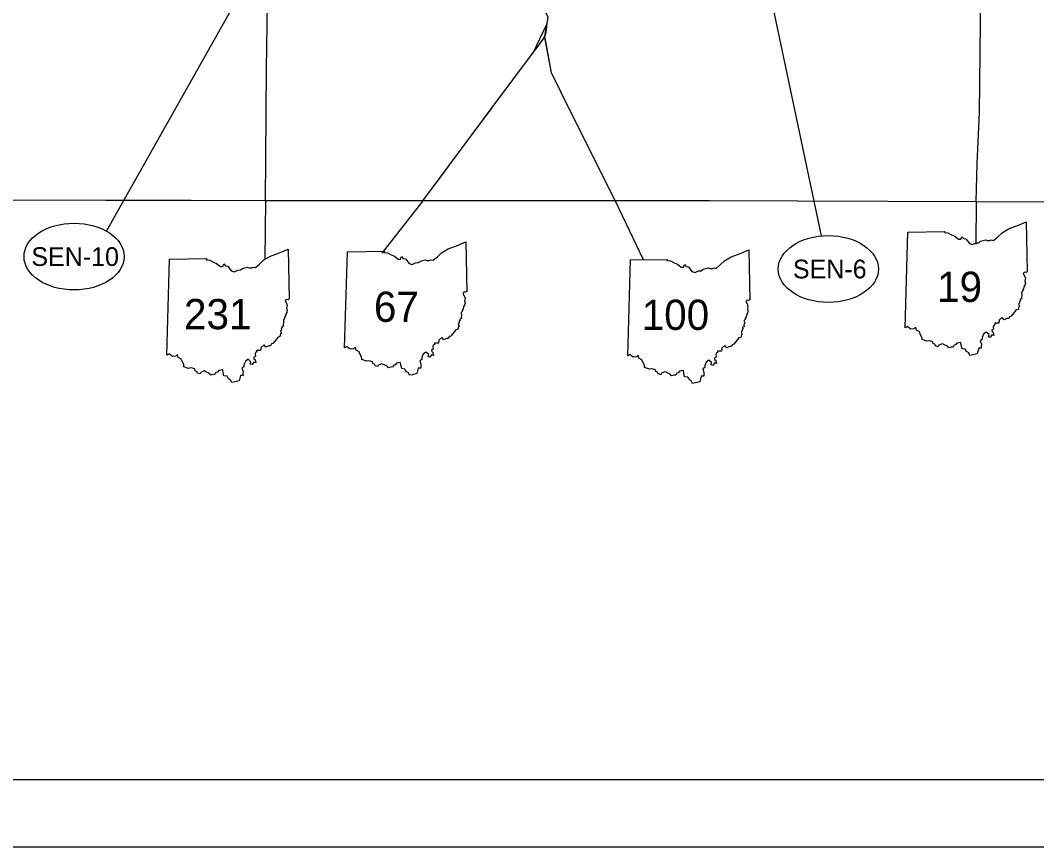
# Model space of a CAD drawing. Extents: x 0 to 882, y 0 to 440.
# Drawn here: x 275.2 to 427.4, y 0 to 123.7 of the extents above; entities that cross this region are included whole.
import ezdxf

# ---------------------------------------------------------------- set-up
doc = ezdxf.new("R2010")
doc.units = 0
for name, color, linetype in [('GM_X_County', 7, 'Continuous'), ('GM_X_State_Route', 7, 'Continuous'), ('PV_P_Text', 7, 'Continuous'), ('RD_P_Fence', 7, 'Continuous'), ('SH_Border', 7, 'Continuous'), ('SH_Cut_Line', 7, 'Continuous'), ('SH_Data', 7, 'Continuous')]:
    doc.layers.add(name, color=color, linetype=linetype)

msp = doc.modelspace()

# ---------------------------------------------------------------- linework, layer by layer
at = {"layer": 'GM_X_County'}
msp.add_lwpolyline([(431.55, 96.47), (418.34, 96.52), (405.13, 96.59), (391.64, 96.65), (391.54, 96.65), (378.39, 96.68), (378.35, 96.67), (364.27, 96.7), (351.77, 96.69), (343.39, 96.66), (338.49, 96.67), (335.48, 96.66), (317.08, 96.69), (311.95, 96.7), (300.8, 96.71), (298.62, 96.72), (288.73, 96.73), (288.04, 96.73), (272.14, 96.76)], dxfattribs=at)
at = {"layer": 'GM_X_State_Route'}
for p, q in [((311.95, 96.7), (311.86, 87.89)), ((335.48, 96.66), (329.38, 88.85)), ((364.27, 96.7), (368.48, 87.89)), ((418.34, 96.52), (418.3, 90.19))]:
    msp.add_line(p, q, dxfattribs=at)
for points in [[(312.11, 116.42), (312.31, 129.67), (312.36, 136.32), (312.5, 150.5), (312.51, 150.79), (312.57, 153.89), (312.59, 154.82), (312.59, 155.09), (312.23, 156.32)], [(418.34, 96.52), (418.48, 102.28), (418.83, 109.89), (418.99, 123.29), (418.97, 125.8), (418.52, 128.47), (418.31, 129.89), (417.67, 133.85), (417.69, 134.46), (417.82, 135.31), (418.05, 136.45), (418.22, 137.09), (418.36, 137.45), (418.41, 137.62), (418.72, 138), (418.9, 138.18), (418.97, 138.29), (419.04, 138.47), (419.22, 142.98), (419.22, 143.05)], [(353.74, 121.33), (353.89, 121.63), (353.99, 122.26), (354.11, 123.2), (354.24, 124.19)], [(345.88, 110.66), (352.04, 118.95), (352.74, 119.84), (353.51, 120.9), (353.74, 121.33)], [(364.27, 96.7), (361.27, 102.72), (357.65, 109.93), (354.78, 115.84), (353.86, 120.59), (353.74, 121.33)], [(312.04, 109.67), (312.04, 109.67), (312.05, 109.8), (312.11, 116.42)], [(311.95, 96.7), (312.04, 109.67)], [(335.48, 96.66), (338.49, 100.66), (340.32, 103.23), (345.86, 110.62), (345.88, 110.66)]]:
    msp.add_lwpolyline(points, dxfattribs=at)
at = {"layer": 'PV_P_Text'}
for p, q in [((407.69, 77.65), (408.09, 92.01)), ((407.69, 77.65), (408.09, 92.01)), ((323.79, 74.66), (324.2, 89.02)), ((323.79, 74.66), (324.2, 89.02)), ((297.18, 73.57), (297.59, 87.93)), ((297.18, 73.57), (297.59, 87.93)), ((366.16, 73.46), (366.56, 87.82)), ((366.16, 73.46), (366.56, 87.82))]:
    msp.add_line(p, q, dxfattribs=at)
for points in [[(408.09, 92.01), (413.66, 92.1), (413.57, 91.93), (414.1, 91.89), (414.66, 91.59), (415.13, 91.39), (415.71, 90.93), (416.05, 90.94), (416.2, 91.31), (416.46, 91.03), (416.78, 90.97), (417.32, 90.29), (417.77, 90.14), (418.31, 90.37), (418.71, 90.41), (419, 90.64), (419.77, 90.84), (419.98, 90.72), (420.39, 90.75), (420.59, 90.84), (420.94, 90.76), (421.56, 91.28), (422.2, 91.9), (423.19, 92.48), (424.66, 93.03), (425.82, 93.52), (425.99, 86.07)], [(408.09, 92.01), (413.66, 92.1), (413.57, 91.93), (414.1, 91.89), (414.66, 91.59), (415.13, 91.39), (415.71, 90.93), (416.05, 90.94), (416.2, 91.31), (416.46, 91.03), (416.78, 90.97), (417.32, 90.29), (417.77, 90.14), (418.31, 90.37), (418.71, 90.41), (419, 90.64), (419.77, 90.84), (419.98, 90.72), (420.39, 90.75), (420.59, 90.84), (420.94, 90.76), (421.56, 91.28), (422.2, 91.9), (423.19, 92.48), (424.66, 93.03), (425.82, 93.52), (425.99, 86.07)], [(324.2, 89.02), (329.77, 89.12), (329.68, 88.94), (330.21, 88.91), (330.77, 88.6), (331.24, 88.41), (331.82, 87.95), (332.16, 87.96), (332.31, 88.33), (332.57, 88.04), (332.89, 87.99), (333.43, 87.3), (333.88, 87.15), (334.42, 87.39), (334.82, 87.43), (335.11, 87.66), (335.88, 87.86), (336.09, 87.74), (336.49, 87.76), (336.7, 87.85), (337.05, 87.77), (337.67, 88.3), (338.31, 88.91), (339.3, 89.49), (340.77, 90.04), (341.93, 90.54), (342.1, 83.08)], [(324.2, 89.02), (329.77, 89.12), (329.68, 88.94), (330.21, 88.91), (330.77, 88.6), (331.24, 88.41), (331.82, 87.95), (332.16, 87.96), (332.31, 88.33), (332.57, 88.04), (332.89, 87.99), (333.43, 87.3), (333.88, 87.15), (334.42, 87.39), (334.82, 87.43), (335.11, 87.66), (335.88, 87.86), (336.09, 87.74), (336.49, 87.76), (336.7, 87.85), (337.05, 87.77), (337.67, 88.3), (338.31, 88.91), (339.3, 89.49), (340.77, 90.04), (341.93, 90.54), (342.1, 83.08)], [(297.59, 87.93), (303.16, 88.02), (303.07, 87.85), (303.6, 87.81), (304.16, 87.51), (304.63, 87.31), (305.21, 86.86), (305.55, 86.86), (305.7, 87.24), (305.96, 86.95), (306.28, 86.9), (306.82, 86.21), (307.27, 86.06), (307.81, 86.29), (308.21, 86.33), (308.5, 86.57), (309.26, 86.77), (309.48, 86.65), (309.88, 86.67), (310.09, 86.76), (310.44, 86.68), (311.06, 87.2), (311.7, 87.82), (312.69, 88.4), (314.16, 88.95), (315.32, 89.44), (315.49, 81.99)], [(297.59, 87.93), (303.16, 88.02), (303.07, 87.85), (303.6, 87.81), (304.16, 87.51), (304.63, 87.31), (305.21, 86.86), (305.55, 86.86), (305.7, 87.24), (305.96, 86.95), (306.28, 86.9), (306.82, 86.21), (307.27, 86.06), (307.81, 86.29), (308.21, 86.33), (308.5, 86.57), (309.26, 86.77), (309.48, 86.65), (309.88, 86.67), (310.09, 86.76), (310.44, 86.68), (311.06, 87.2), (311.7, 87.82), (312.69, 88.4), (314.16, 88.95), (315.32, 89.44), (315.49, 81.99)], [(366.56, 87.82), (372.13, 87.91), (372.04, 87.74), (372.57, 87.7), (373.13, 87.4), (373.6, 87.2), (374.18, 86.75), (374.52, 86.75), (374.67, 87.13), (374.94, 86.84), (375.25, 86.78), (375.79, 86.1), (376.24, 85.95), (376.78, 86.18), (377.18, 86.22), (377.47, 86.46), (378.24, 86.65), (378.45, 86.54), (378.86, 86.56), (379.06, 86.65), (379.41, 86.57), (380.03, 87.09), (380.67, 87.71), (381.66, 88.29), (383.13, 88.84), (384.29, 89.33), (384.46, 81.88)], [(366.56, 87.82), (372.13, 87.91), (372.04, 87.74), (372.57, 87.7), (373.13, 87.4), (373.6, 87.2), (374.18, 86.75), (374.52, 86.75), (374.67, 87.13), (374.94, 86.84), (375.25, 86.78), (375.79, 86.1), (376.24, 85.95), (376.78, 86.18), (377.18, 86.22), (377.47, 86.46), (378.24, 86.65), (378.45, 86.54), (378.86, 86.56), (379.06, 86.65), (379.41, 86.57), (380.03, 87.09), (380.67, 87.71), (381.66, 88.29), (383.13, 88.84), (384.29, 89.33), (384.46, 81.88)], [(425.99, 86.07), (425.82, 85.96), (425.55, 86.01), (425.37, 85.8), (425.59, 85.45), (425.7, 85.08), (425.6, 84.68), (425.7, 84.34), (425.63, 84.06), (425.47, 83.78), (425.41, 83.52), (425.26, 83.24), (425.28, 83.08), (425.14, 82.96), (425.17, 82.49), (425.1, 82.23), (425.12, 82.01), (424.9, 81.95), (424.95, 81.77), (424.81, 81.62), (424.84, 81.38), (424.68, 81.22), (424.84, 80.91), (424.71, 80.81), (424.61, 80.43), (424.32, 80.35), (423.76, 79.66), (423.56, 79.4), (423.33, 79.33), (423.21, 79.06), (422.93, 79.06), (422.51, 78.87), (422.24, 79.19), (421.77, 78.81), (421.72, 78.36), (421.12, 78.37), (421.14, 78.15), (421.01, 78.08), (420.88, 77.85), (420.95, 77.45), (420.67, 77.35), (420.71, 77.11), (420.89, 76.97), (420.97, 76.52), (420.67, 76.61), (420.42, 76.24), (420.17, 76.33), (420.26, 76.65), (419.83, 77.03), (419.43, 76.72), (419.22, 76.23), (419.22, 75.9), (418.92, 75.7), (419.11, 75.23), (419.08, 74.91), (419.08, 74.61), (418.71, 74.62), (418.48, 73.79)], [(425.99, 86.07), (425.82, 85.96), (425.55, 86.01), (425.37, 85.8), (425.59, 85.45), (425.7, 85.08), (425.6, 84.68), (425.7, 84.34), (425.63, 84.06), (425.47, 83.78), (425.41, 83.52), (425.26, 83.24), (425.28, 83.08), (425.14, 82.96), (425.17, 82.49), (425.1, 82.23), (425.12, 82.01), (424.9, 81.95), (424.95, 81.77), (424.81, 81.62), (424.84, 81.38), (424.68, 81.22), (424.84, 80.91), (424.71, 80.81), (424.61, 80.43), (424.32, 80.35), (423.76, 79.66), (423.56, 79.4), (423.33, 79.33), (423.21, 79.06), (422.93, 79.06), (422.51, 78.87), (422.24, 79.19), (421.77, 78.81), (421.72, 78.36), (421.12, 78.37), (421.14, 78.15), (421.01, 78.08), (420.88, 77.85), (420.95, 77.45), (420.67, 77.35), (420.71, 77.11), (420.89, 76.97), (420.97, 76.52), (420.67, 76.61), (420.42, 76.24), (420.17, 76.33), (420.26, 76.65), (419.83, 77.03), (419.43, 76.72), (419.22, 76.23), (419.22, 75.9), (418.92, 75.7), (419.11, 75.23), (419.08, 74.91), (419.08, 74.61), (418.71, 74.62), (418.48, 73.79)], [(342.1, 83.08), (341.93, 82.98), (341.66, 83.03), (341.48, 82.82), (341.7, 82.47), (341.81, 82.1), (341.71, 81.69), (341.81, 81.36), (341.74, 81.08), (341.57, 80.8), (341.52, 80.53), (341.37, 80.25), (341.39, 80.1), (341.25, 79.97), (341.27, 79.51), (341.21, 79.25), (341.23, 79.03), (341.01, 78.97), (341.06, 78.78), (340.92, 78.64), (340.95, 78.4), (340.79, 78.24), (340.94, 77.93), (340.82, 77.83), (340.72, 77.45), (340.43, 77.37), (339.87, 76.67), (339.67, 76.41), (339.44, 76.35), (339.32, 76.08), (339.04, 76.08), (338.62, 75.89), (338.35, 76.21), (337.88, 75.82), (337.82, 75.37), (337.23, 75.39), (337.25, 75.16), (337.11, 75.1), (336.99, 74.87), (337.06, 74.47), (336.78, 74.36), (336.82, 74.13), (337, 73.99), (337.08, 73.54), (336.78, 73.63), (336.53, 73.25), (336.28, 73.34), (336.37, 73.66), (335.94, 74.04), (335.54, 73.74), (335.33, 73.25), (335.33, 72.92), (335.03, 72.72), (335.22, 72.25), (335.18, 71.93), (335.19, 71.62), (334.82, 71.63), (334.59, 70.81)], [(342.1, 83.08), (341.93, 82.98), (341.66, 83.03), (341.48, 82.82), (341.7, 82.47), (341.81, 82.1), (341.71, 81.69), (341.81, 81.36), (341.74, 81.08), (341.57, 80.8), (341.52, 80.53), (341.37, 80.25), (341.39, 80.1), (341.25, 79.97), (341.27, 79.51), (341.21, 79.25), (341.23, 79.03), (341.01, 78.97), (341.06, 78.78), (340.92, 78.64), (340.95, 78.4), (340.79, 78.24), (340.94, 77.93), (340.82, 77.83), (340.72, 77.45), (340.43, 77.37), (339.87, 76.67), (339.67, 76.41), (339.44, 76.35), (339.32, 76.08), (339.04, 76.08), (338.62, 75.89), (338.35, 76.21), (337.88, 75.82), (337.82, 75.37), (337.23, 75.39), (337.25, 75.16), (337.11, 75.1), (336.99, 74.87), (337.06, 74.47), (336.78, 74.36), (336.82, 74.13), (337, 73.99), (337.08, 73.54), (336.78, 73.63), (336.53, 73.25), (336.28, 73.34), (336.37, 73.66), (335.94, 74.04), (335.54, 73.74), (335.33, 73.25), (335.33, 72.92), (335.03, 72.72), (335.22, 72.25), (335.18, 71.93), (335.19, 71.62), (334.82, 71.63), (334.59, 70.81)], [(315.49, 81.99), (315.31, 81.88), (315.05, 81.93), (314.87, 81.72), (315.09, 81.37), (315.19, 81.01), (315.1, 80.6), (315.19, 80.27), (315.13, 79.98), (314.96, 79.71), (314.91, 79.44), (314.76, 79.16), (314.77, 79), (314.64, 78.88), (314.66, 78.41), (314.59, 78.15), (314.62, 77.93), (314.4, 77.87), (314.45, 77.69), (314.31, 77.55), (314.34, 77.3), (314.18, 77.15), (314.33, 76.83), (314.21, 76.73), (314.11, 76.35), (313.82, 76.28), (313.26, 75.58), (313.06, 75.32), (312.83, 75.25), (312.71, 74.98), (312.43, 74.98), (312.01, 74.79), (311.74, 75.12), (311.27, 74.73), (311.21, 74.28), (310.61, 74.29), (310.64, 74.07), (310.5, 74), (310.38, 73.78), (310.45, 73.37), (310.17, 73.27), (310.21, 73.04), (310.39, 72.89), (310.47, 72.45), (310.17, 72.54), (309.92, 72.16), (309.67, 72.25), (309.75, 72.57), (309.33, 72.95), (308.93, 72.64), (308.72, 72.15), (308.72, 71.82), (308.42, 71.62), (308.61, 71.15), (308.57, 70.83), (308.58, 70.53), (308.2, 70.54), (307.98, 69.71)], [(315.49, 81.99), (315.31, 81.88), (315.05, 81.93), (314.87, 81.72), (315.09, 81.37), (315.19, 81.01), (315.1, 80.6), (315.19, 80.27), (315.13, 79.98), (314.96, 79.71), (314.91, 79.44), (314.76, 79.16), (314.77, 79), (314.64, 78.88), (314.66, 78.41), (314.59, 78.15), (314.62, 77.93), (314.4, 77.87), (314.45, 77.69), (314.31, 77.55), (314.34, 77.3), (314.18, 77.15), (314.33, 76.83), (314.21, 76.73), (314.11, 76.35), (313.82, 76.28), (313.26, 75.58), (313.06, 75.32), (312.83, 75.25), (312.71, 74.98), (312.43, 74.98), (312.01, 74.79), (311.74, 75.12), (311.27, 74.73), (311.21, 74.28), (310.61, 74.29), (310.64, 74.07), (310.5, 74), (310.38, 73.78), (310.45, 73.37), (310.17, 73.27), (310.21, 73.04), (310.39, 72.89), (310.47, 72.45), (310.17, 72.54), (309.92, 72.16), (309.67, 72.25), (309.75, 72.57), (309.33, 72.95), (308.93, 72.64), (308.72, 72.15), (308.72, 71.82), (308.42, 71.62), (308.61, 71.15), (308.57, 70.83), (308.58, 70.53), (308.2, 70.54), (307.98, 69.71)], [(384.46, 81.88), (384.29, 81.77), (384.02, 81.82), (383.84, 81.61), (384.06, 81.26), (384.17, 80.9), (384.08, 80.49), (384.17, 80.15), (384.1, 79.87), (383.94, 79.59), (383.88, 79.33), (383.74, 79.05), (383.75, 78.89), (383.61, 78.77), (383.64, 78.3), (383.57, 78.04), (383.59, 77.82), (383.37, 77.76), (383.42, 77.58), (383.28, 77.44), (383.31, 77.19), (383.15, 77.03), (383.31, 76.72), (383.18, 76.62), (383.08, 76.24), (382.8, 76.17), (382.23, 75.47), (382.03, 75.21), (381.8, 75.14), (381.68, 74.87), (381.4, 74.87), (380.99, 74.68), (380.72, 75.01), (380.24, 74.62), (380.19, 74.17), (379.59, 74.18), (379.61, 73.96), (379.48, 73.89), (379.35, 73.66), (379.43, 73.26), (379.14, 73.16), (379.18, 72.92), (379.36, 72.78), (379.44, 72.33), (379.14, 72.43), (378.9, 72.05), (378.64, 72.14), (378.73, 72.46), (378.3, 72.84), (377.9, 72.53), (377.69, 72.04), (377.69, 71.71), (377.39, 71.51), (377.58, 71.04), (377.55, 70.72), (377.55, 70.42), (377.18, 70.43), (376.95, 69.6)], [(384.46, 81.88), (384.29, 81.77), (384.02, 81.82), (383.84, 81.61), (384.06, 81.26), (384.17, 80.9), (384.08, 80.49), (384.17, 80.15), (384.1, 79.87), (383.94, 79.59), (383.88, 79.33), (383.74, 79.05), (383.75, 78.89), (383.61, 78.77), (383.64, 78.3), (383.57, 78.04), (383.59, 77.82), (383.37, 77.76), (383.42, 77.58), (383.28, 77.44), (383.31, 77.19), (383.15, 77.03), (383.31, 76.72), (383.18, 76.62), (383.08, 76.24), (382.8, 76.17), (382.23, 75.47), (382.03, 75.21), (381.8, 75.14), (381.68, 74.87), (381.4, 74.87), (380.99, 74.68), (380.72, 75.01), (380.24, 74.62), (380.19, 74.17), (379.59, 74.18), (379.61, 73.96), (379.48, 73.89), (379.35, 73.66), (379.43, 73.26), (379.14, 73.16), (379.18, 72.92), (379.36, 72.78), (379.44, 72.33), (379.14, 72.43), (378.9, 72.05), (378.64, 72.14), (378.73, 72.46), (378.3, 72.84), (377.9, 72.53), (377.69, 72.04), (377.69, 71.71), (377.39, 71.51), (377.58, 71.04), (377.55, 70.72), (377.55, 70.42), (377.18, 70.43), (376.95, 69.6)], [(418.48, 73.79), (417.83, 73.63), (417.38, 73.54), (417.22, 73.91), (416.9, 74.11), (416.69, 74.49), (416.22, 74.54), (416.11, 75.06), (416.06, 75.48), (415.43, 75.37), (415.25, 75.12), (415.03, 75.05), (414.9, 74.79), (414.59, 74.77), (414.26, 74.65), (414.05, 74.9), (413.51, 75.15), (413.27, 75.29), (412.76, 75.08), (412.65, 74.84), (412.25, 74.95), (412.15, 75.22), (411.91, 75.3), (411.86, 75.58), (411.34, 75.74), (410.94, 75.68), (410.23, 75.91), (410.19, 76.28), (409.95, 76.74), (409.83, 77.06), (409.38, 77.3), (409.29, 77.68), (409.15, 77.67), (409.02, 77.52), (408.52, 77.45), (408.33, 77.6), (408.05, 77.86), (407.69, 77.65)], [(418.48, 73.79), (417.83, 73.63), (417.38, 73.54), (417.22, 73.91), (416.9, 74.11), (416.69, 74.49), (416.22, 74.54), (416.11, 75.06), (416.06, 75.48), (415.43, 75.37), (415.25, 75.12), (415.03, 75.05), (414.9, 74.79), (414.59, 74.77), (414.26, 74.65), (414.05, 74.9), (413.51, 75.15), (413.27, 75.29), (412.76, 75.08), (412.65, 74.84), (412.25, 74.95), (412.15, 75.22), (411.91, 75.3), (411.86, 75.58), (411.34, 75.74), (410.94, 75.68), (410.23, 75.91), (410.19, 76.28), (409.95, 76.74), (409.83, 77.06), (409.38, 77.3), (409.29, 77.68), (409.15, 77.67), (409.02, 77.52), (408.52, 77.45), (408.33, 77.6), (408.05, 77.86), (407.69, 77.65)], [(334.59, 70.81), (333.94, 70.65), (333.49, 70.56), (333.33, 70.93), (333.01, 71.13), (332.8, 71.5), (332.33, 71.56), (332.22, 72.07), (332.17, 72.49), (331.54, 72.39), (331.36, 72.13), (331.14, 72.06), (331.01, 71.81), (330.7, 71.78), (330.37, 71.66), (330.16, 71.92), (329.62, 72.17), (329.38, 72.3), (328.87, 72.1), (328.76, 71.86), (328.36, 71.96), (328.26, 72.23), (328.02, 72.31), (327.97, 72.6), (327.45, 72.75), (327.05, 72.69), (326.34, 72.92), (326.3, 73.3), (326.06, 73.76), (325.94, 74.07), (325.49, 74.32), (325.4, 74.7), (325.26, 74.69), (325.13, 74.53), (324.63, 74.46), (324.44, 74.62), (324.16, 74.88), (323.79, 74.66)], [(334.59, 70.81), (333.94, 70.65), (333.49, 70.56), (333.33, 70.93), (333.01, 71.13), (332.8, 71.5), (332.33, 71.56), (332.22, 72.07), (332.17, 72.49), (331.54, 72.39), (331.36, 72.13), (331.14, 72.06), (331.01, 71.81), (330.7, 71.78), (330.37, 71.66), (330.16, 71.92), (329.62, 72.17), (329.38, 72.3), (328.87, 72.1), (328.76, 71.86), (328.36, 71.96), (328.26, 72.23), (328.02, 72.31), (327.97, 72.6), (327.45, 72.75), (327.05, 72.69), (326.34, 72.92), (326.3, 73.3), (326.06, 73.76), (325.94, 74.07), (325.49, 74.32), (325.4, 74.7), (325.26, 74.69), (325.13, 74.53), (324.63, 74.46), (324.44, 74.62), (324.16, 74.88), (323.79, 74.66)], [(307.98, 69.71), (307.33, 69.56), (306.88, 69.46), (306.72, 69.84), (306.39, 70.03), (306.18, 70.41), (305.72, 70.46), (305.61, 70.98), (305.56, 71.4), (304.93, 71.3), (304.75, 71.04), (304.53, 70.97), (304.4, 70.71), (304.09, 70.69), (303.76, 70.57), (303.55, 70.82), (303.01, 71.08), (302.76, 71.21), (302.26, 71), (302.15, 70.76), (301.75, 70.87), (301.65, 71.14), (301.41, 71.22), (301.35, 71.51), (300.83, 71.66), (300.43, 71.6), (299.73, 71.83), (299.69, 72.2), (299.45, 72.66), (299.32, 72.98), (298.88, 73.22), (298.79, 73.6), (298.65, 73.59), (298.52, 73.44), (298.02, 73.37), (297.83, 73.52), (297.55, 73.79), (297.18, 73.57)], [(307.98, 69.71), (307.33, 69.56), (306.88, 69.46), (306.72, 69.84), (306.39, 70.03), (306.18, 70.41), (305.72, 70.46), (305.61, 70.98), (305.56, 71.4), (304.93, 71.3), (304.75, 71.04), (304.53, 70.97), (304.4, 70.71), (304.09, 70.69), (303.76, 70.57), (303.55, 70.82), (303.01, 71.08), (302.76, 71.21), (302.26, 71), (302.15, 70.76), (301.75, 70.87), (301.65, 71.14), (301.41, 71.22), (301.35, 71.51), (300.83, 71.66), (300.43, 71.6), (299.73, 71.83), (299.69, 72.2), (299.45, 72.66), (299.32, 72.98), (298.88, 73.22), (298.79, 73.6), (298.65, 73.59), (298.52, 73.44), (298.02, 73.37), (297.83, 73.52), (297.55, 73.79), (297.18, 73.57)], [(376.95, 69.6), (376.3, 69.44), (375.85, 69.35), (375.69, 69.72), (375.37, 69.92), (375.16, 70.3), (374.69, 70.35), (374.58, 70.87), (374.53, 71.29), (373.9, 71.19), (373.72, 70.93), (373.5, 70.86), (373.37, 70.6), (373.06, 70.58), (372.73, 70.46), (372.52, 70.71), (371.98, 70.97), (371.74, 71.1), (371.23, 70.89), (371.12, 70.65), (370.72, 70.76), (370.63, 71.03), (370.38, 71.11), (370.33, 71.39), (369.81, 71.55), (369.41, 71.49), (368.7, 71.72), (368.66, 72.09), (368.42, 72.55), (368.3, 72.87), (367.85, 73.11), (367.76, 73.49), (367.62, 73.48), (367.49, 73.33), (367, 73.26), (366.8, 73.41), (366.52, 73.68), (366.16, 73.46)], [(376.95, 69.6), (376.3, 69.44), (375.85, 69.35), (375.69, 69.72), (375.37, 69.92), (375.16, 70.3), (374.69, 70.35), (374.58, 70.87), (374.53, 71.29), (373.9, 71.19), (373.72, 70.93), (373.5, 70.86), (373.37, 70.6), (373.06, 70.58), (372.73, 70.46), (372.52, 70.71), (371.98, 70.97), (371.74, 71.1), (371.23, 70.89), (371.12, 70.65), (370.72, 70.76), (370.63, 71.03), (370.38, 71.11), (370.33, 71.39), (369.81, 71.55), (369.41, 71.49), (368.7, 71.72), (368.66, 72.09), (368.42, 72.55), (368.3, 72.87), (367.85, 73.11), (367.76, 73.49), (367.62, 73.48), (367.49, 73.33), (367, 73.26), (366.8, 73.41), (366.52, 73.68), (366.16, 73.46)]]:
    msp.add_lwpolyline(points, dxfattribs=at)
at = {"layer": 'RD_P_Fence'}
for points in [[(364.27, 96.7), (357.65, 109.93), (354.78, 115.84), (353.74, 121.33), (354.24, 124.19), (352.46, 127.61), (341.85, 142.9), (340.8, 144.52), (339.05, 146.23), (338.86, 155.61), (332.91, 159.33), (321.07, 182.72), (316.82, 190.88)], [(335.48, 96.66), (345.88, 110.66), (352.04, 118.95), (354.11, 123.2)]]:
    msp.add_lwpolyline(points, dxfattribs=at)
at = {"layer": 'SH_Border'}
msp.add_lwpolyline([(30, 430), (670, 430), (670, 10), (30, 10)], close=True, dxfattribs=at)
at = {"layer": 'SH_Cut_Line'}
msp.add_lwpolyline([(0, 0), (680, 0), (680, 440), (0, 440)], close=True, dxfattribs=at)
at = {"layer": 'SH_Data'}
for p, q in [((288.13, 92.15), (329.62, 165.82)), ((395.16, 91.42), (380.67, 160.23))]:
    msp.add_line(p, q, dxfattribs=at)
for centre in [(283.29, 88.33), (396.2, 86.47)]:
    msp.add_ellipse(centre, major_axis=(7.5, 0), ratio=0.666667, dxfattribs=at)

# ---------------------------------------------------------------- texts
at = {"layer": 'PV_P_Text'}
for s, p in [('19', (412.48, 81.54)), ('67', (328.17, 78.56)), ('231', (299.74, 77.46)), ('100', (368.26, 77.35))]:
    msp.add_text(s, height=4.528, dxfattribs=at).set_placement(p)
at = {"layer": 'SH_Data'}
for s, p in [('SEN-10', (276.89, 86.93)), ('SEN-6', (390.9, 85.07))]:
    msp.add_text(s, height=2.8, dxfattribs=at).set_placement(p)

doc.saveas('drawing.dxf')
